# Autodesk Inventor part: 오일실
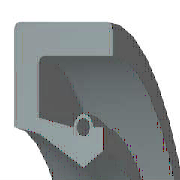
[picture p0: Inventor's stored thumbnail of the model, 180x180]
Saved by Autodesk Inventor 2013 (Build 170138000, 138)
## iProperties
IsCustomPart: 1
Company: 한국ATC센터
Created: 2014-10
Part Number: 오일실
Material: 고무
Description: 오일-실
Document SubType Name: Modeling
Standard: KS B 2804
Designer: 한국ATC센터
Standards Organization: KS
Language: ko-KR
Size Designation: S - 25 40 8
Categories: <MemberInstance><Categories><Category DisplayName="샤프트 부품" InternalName="7f7aeb1f-a693-4053-b835-cee3144e0d98" Mnemonic="SHFT"><Category DisplayName="실링" Intern
Density: 0.93 g/cm^3
Mass: 2.48215 g
Surface Area: 40.3381 cm^2
Volume: 2.66898 cm^3
Author: KYOUNG IL JANG
Revision Number: 1
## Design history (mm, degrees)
revolve "본체" stored, may be unused: angle "d17" = 90 deg
revolve "스프링1" stored, may be unused: angle "d18" = 90 deg
body "Solid1"
sketch "스케치1"
  geometry: L1 (0, 20)-(8, 20); L2 (8, 20)-(8, 18.75); L3 (8, 18.75)-(1.75, 18.75); L4 (0, 20)-(0, 14.6); L5 (0, 14.6)-(1.75, 14.25); L6 (1.75, 14.25)-(4.9, 12.5); L7 (4.9, 12.5)-(0, 12.5); L8 (6.3, 13.375)-(6.3, 14.6); L9 (0, 0)-(9.586, 0) reference; L10 (4.9, 12.5)-(6.3, 13.375); L11 (0, 18)-(0, -3) reference; L12 (-1.917, 0)-(11.503, 0) reference; L13 (4.2, 14.6)-(1.75, 15.09); L14 (1.75, 15.09)-(1.75, 18.75); L15 (6.3, 14.6)-(5.6, 14.6); C1 r 0.455 at (4.9, 14.6); A1 r 0.7 centre (4.9, 14.6) between (5.6, 14.6) and (4.2, 14.6)
  constraints: 26 end point, 5 horizontal alignment, 4 perpendicular, 2 centre point, 2 collinear, 2 horizontal, 2 parallel, 2 point on circle, 2 point on line, 2 vertical alignment, 1 coincident
  dimensions: "d0" = 40 diameter of L1 L9 (= SD2); "d1" = 26.75 diameter of L8.start L9 (= ABDM); "d2" = 1.25 distance of L1.end L2.end (computed from SD); "d3" = 0.91 diameter of C1 (= SPDI); "d4" = 1.4 diameter of A1 (= SPDA); "d5" = 25 diameter of L6.end L9 (= NND); "d6" = 28.5 diameter of L5.end L9 (= TKDM); "d7" = 29.2 diameter of L4.end L9 (= HLDM); "d8" = 4.9 distance from line of C1.centre L4 (= SPDST); "d9" = 6.3 distance between parallel lines of L8 L4 (= SDI); "d10" = 8 distance between parallel lines of L2 L4 (= SWDT); "d12" = 1.75 distance between parallel lines of L14 L4 (= SD)
fillet "모깎기1" dims "d11" = 0.3 (= RR)
other parameters: "SD2" = 40 [user parameter; used in 1 equation term], "SWDT" = 8 [user parameter; used in 1 equation term], "RR" = 0.3 [user parameter; used in 1 equation term], "SD" = 1.75 [user parameter; used in 2 equation terms], "NND" = 25 [user parameter; used in 1 equation term], "SPDA" = 1.4 [user parameter; used in 1 equation term], "SPDI" = 0.91 [user parameter; used in 1 equation term], "TKDM" = 28.5 [user parameter; used in 1 equation term], "HLDM" = 29.2 [user parameter; used in 1 equation term], "ABDM" = 26.75 [user parameter; used in 1 equation term], "SDI" = 6.3 [user parameter; used in 1 equation term], "SPDST" = 4.9 [user parameter; used in 1 equation term], "d13" = 0, "d14" = 0, "d15" = 0, "LAB" = 0.35 [user parameter]
